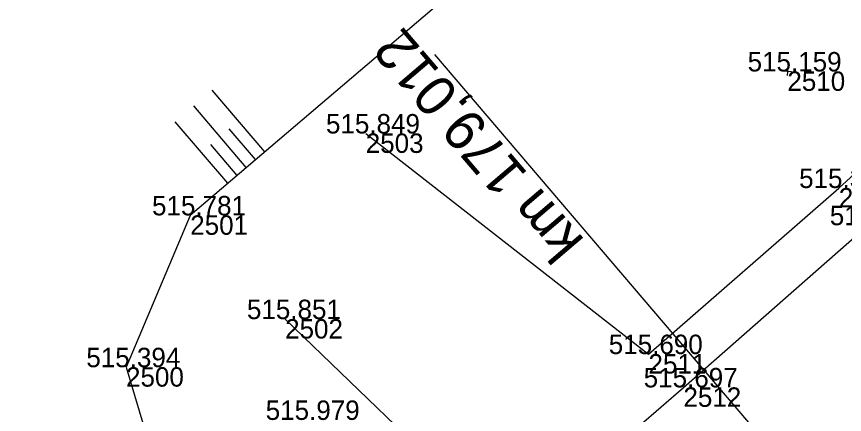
# Model space of a CAD drawing. Extents: x -1234191 to 23050, y -1290331 to -741191.
# Drawn here: x -865386.4 to -865335.3, y -1104882.4 to -1104857.8 of the extents above; entities that cross this region are included whole.
import ezdxf

# ---------------------------------------------------------------- set-up
doc = ezdxf.new("R2010")
doc.units = 0
for name, color, linetype in [('Vrstva 16', 7, 'Continuous'), ('Vrstva 48', 7, 'Continuous'), ('Vrstva 49', 7, 'Continuous'), ('Vrstva 6', 7, 'Continuous'), ('Vrstva 60', 7, 'Continuous'), ('Vrstva 61', 7, 'Continuous')]:
    doc.layers.add(name, color=color, linetype=linetype)

msp = doc.modelspace()

# ---------------------------------------------------------------- linework, layer by layer
at = {"layer": 'Vrstva 16'}
for points in [[(-865364.804, -1104865.035), (-865347.352, -1104878.663), (-865335.605, -1104868.404), (-865321.309, -1104855.308), (-865306.813, -1104842.156), (-865307.637, -1104841.221), (-865285.52, -1104820.848), (-865269.807, -1104806.574), (-865250.423, -1104788.913), (-865250.512, -1104784.949), (-865237.108, -1104772.85)], [(-865365.284, -1104917.689), (-865373.91, -1104910.569), (-865349.316, -1104884.315), (-865345.195, -1104880.72), (-865333.802, -1104870.703), (-865303.92, -1104843.352), (-865301.817, -1104845.58), (-865280.658, -1104826.166), (-865276.342, -1104822.554)], [(-865344.099, -1104890.937), (-865354.25, -1104900.181), (-865365.284, -1104917.689), (-865373.91, -1104910.569), (-865349.316, -1104884.315), (-865345.195, -1104880.72), (-865333.802, -1104870.703), (-865303.92, -1104843.352)], [(-865430.786, -1104982.4), (-865428.911, -1104978.946), (-865426.841, -1104980.119), (-865421.86, -1104972.64), (-865410.634, -1104959.807), (-865406.775, -1104953.15), (-865404.756, -1104949.654), (-865400.925, -1104943.282), (-865398.82, -1104944.645), (-865398.21, -1104943.964), (-865394.321, -1104937.476), (-865392.206, -1104933.959), (-865388.367, -1104927.392), (-865383.861, -1104920.707), (-865376.315, -1104908.61), (-865368.059, -1104898.222), (-865357.858, -1104888.003), (-865369.779, -1104876.503)]]:
    msp.add_lwpolyline(points, dxfattribs=at)
at = {"layer": 'Vrstva 48'}
for p, q in [((-865371.031, -1104866.164), (-865374.277, -1104862.361)), ((-865372.173, -1104867.138), (-865375.418, -1104863.334)), ((-865373.314, -1104868.111), (-865376.559, -1104864.308)), ((-865371.602, -1104866.651), (-865373.225, -1104864.749)), ((-865372.743, -1104867.625), (-865374.366, -1104865.723))]:
    msp.add_line(p, q, dxfattribs=at)
at = {"layer": 'Vrstva 49'}
for p, q in [((-865338.53, -1104861.223), (-865339.028, -1104861.183)), ((-865338.759, -1104860.954), (-865338.799, -1104861.452))]:
    msp.add_line(p, q, dxfattribs=at)
msp.add_lwpolyline([(-865171.114, -1104750.378), (-865191.358, -1104740.165), (-865202.899, -1104737.779), (-865216.924, -1104745.887), (-865226.364, -1104743.666), (-865239.531, -1104749.856), (-865258.753, -1104770.039), (-865284.883, -1104787.879), (-865308.11, -1104807.741), (-865326.673, -1104834.815), (-865331.084, -1104845.736), (-865343.979, -1104852.325), (-865358.212, -1104855.226), (-865375.636, -1104870.093), (-865379.598, -1104879.473), (-865375.064, -1104894.679), (-865385.012, -1104905.646), (-865402.355, -1104922.203), (-865421.239, -1104947.821), (-865427.839, -1104950.026), (-865433.692, -1104947.296), (-865439.605, -1104965.607)], dxfattribs=at)
at = {"layer": 'Vrstva 6'}
msp.add_line((-865360.561, -1104860.154), (-865325.859, -1104900.843), dxfattribs=at)
at = {"layer": 'Vrstva 60'}
for p, q in [((-865338.779, -1104861.203), (-865338.779, -1104861.203)), ((-865364.804, -1104865.035), (-865364.804, -1104865.035)), ((-865335.605, -1104868.404), (-865335.605, -1104868.404)), ((-865375.636, -1104870.093), (-865375.636, -1104870.093)), ((-865369.779, -1104876.503), (-865369.779, -1104876.503)), ((-865347.352, -1104878.663), (-865347.352, -1104878.663)), ((-865379.598, -1104879.473), (-865379.598, -1104879.473)), ((-865345.195, -1104880.72), (-865345.195, -1104880.72))]:
    msp.add_line(p, q, dxfattribs=at)

# ---------------------------------------------------------------- texts
at = {"layer": 'Vrstva 6'}
msp.add_text('km 179,012', height=2.5, rotation=130.4598, dxfattribs=at).set_placement((-865351.238, -1104871.644))
at = {"layer": 'Vrstva 60'}
for s, p in [('2510', (-865338.779, -1104862.403)), ('2503', (-865364.804, -1104866.235)), ('2514', (-865335.605, -1104869.604)), ('2501', (-865375.636, -1104871.293)), ('2502', (-865369.779, -1104877.703)), ('2511', (-865347.352, -1104879.863)), ('2500', (-865379.598, -1104880.673)), ('2512', (-865345.195, -1104881.92))]:
    msp.add_text(s, height=1.2, dxfattribs=at).set_placement(p)
at = {"layer": 'Vrstva 61'}
for s, p in [('515.159', (-865341.233, -1104861.203)), ('515.849', (-865367.258, -1104865.035)), ('515.342', (-865338.053, -1104868.404)), ('515.781', (-865377.993, -1104870.093)), ('515.431', (-865336.159, -1104870.703)), ('515.851', (-865372.136, -1104876.503)), ('515.690', (-865349.803, -1104878.663)), ('515.394', (-865382.049, -1104879.473)), ('515.697', (-865347.647, -1104880.72)), ('515.979', (-865370.977, -1104882.729))]:
    msp.add_text(s, height=1.2, dxfattribs=at).set_placement(p)

doc.saveas('drawing.dxf')
